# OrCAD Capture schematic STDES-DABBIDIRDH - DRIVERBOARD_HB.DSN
size D
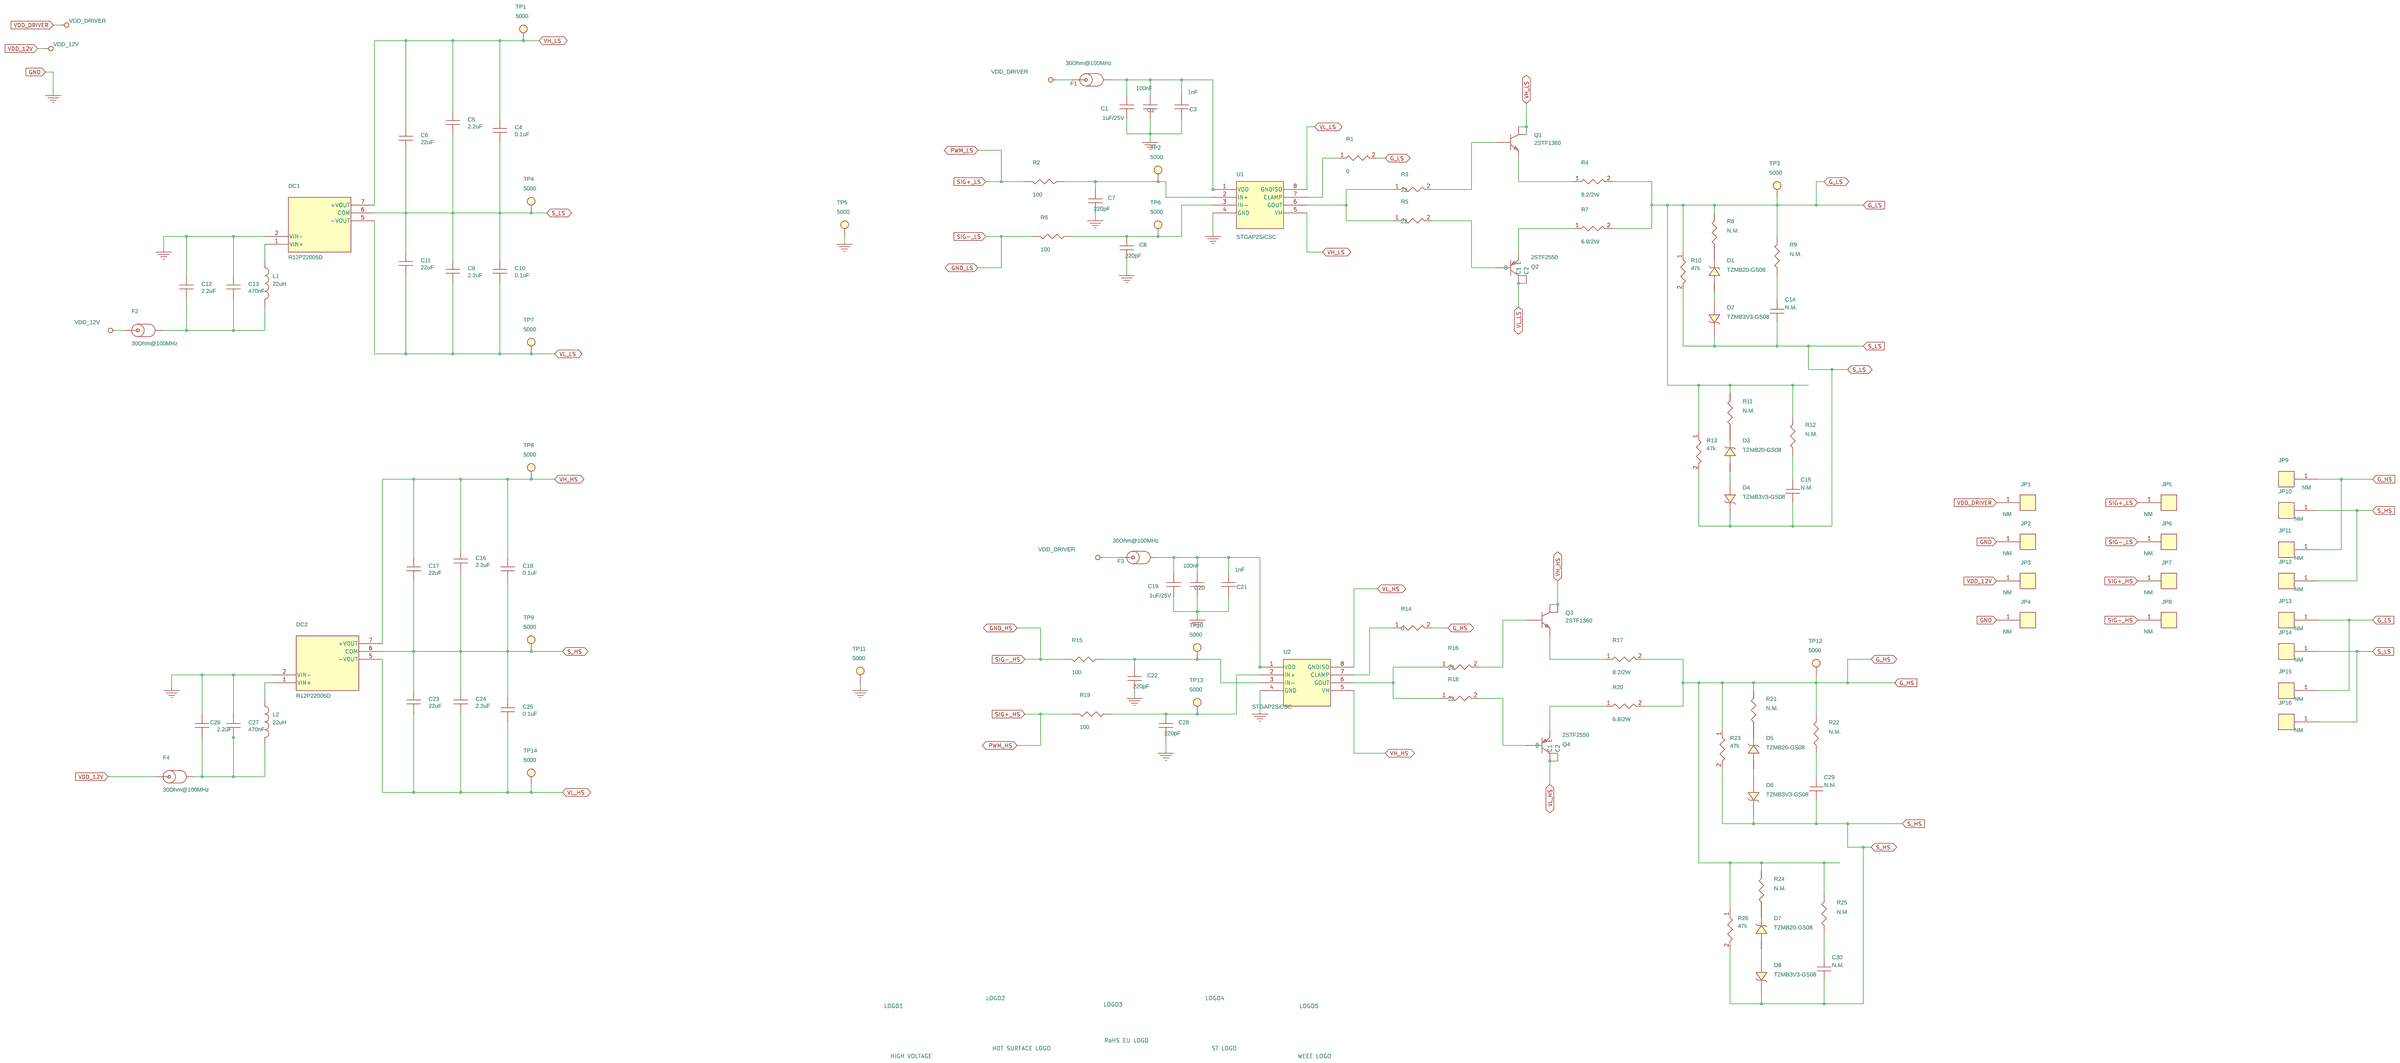
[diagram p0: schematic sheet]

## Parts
C1  1uF/25V  [c_0603]
C2  100nF  [c_0603]
C3  1nF  [C_0603]
C4  0.1uF  [C_0603]
C5  2.2uF  [C_0805]
C6  22uF  [C_1210]
C7  220pF  [c_0603]
C8  220pF  [c_0603]
C9  2.2uF  [C_0805]
C10  0.1uF  [C_0603]
C11  22uF  [C_1210]
C12  2.2uF  [C_0805]
C13  470nF  [C_0805]
C14  N.M.  [C_0603]
C15  N.M.  [C_0603]
C16  2.2uF  [C_0805]
C17  22uF  [C_1210]
C18  0.1uF  [C_0603]
C19  1uF/25V  [c_0603]
C20  100nF  [c_0603]
C21  1nF  [C_0603]
C22  220pF  [c_0603]
C23  22uF  [C_1210]
C24  2.2uF  [C_0805]
C25  0.1uF  [C_0603]
C26  2.2uF  [C_0805]
C27  470nF  [C_0805]
C28  220pF  [c_0603]
C29  N.M.  [C_0603]
C30  N.M.  [C_0603]
D1  TZMB20-GS08  [DIODE_DO-213AC_SOD-80]
D2  TZMB3V3-GS08  [DIODE_DO-213AC_SOD-80]
D3  TZMB20-GS08  [DIODE_DO-213AC_SOD-80]
D4  TZMB3V3-GS08  [DIODE_DO-213AC_SOD-80]
D5  TZMB20-GS08  [DIODE_DO-213AC_SOD-80]
D6  TZMB3V3-GS08  [DIODE_DO-213AC_SOD-80]
D7  TZMB20-GS08  [DIODE_DO-213AC_SOD-80]
D8  TZMB3V3-GS08  [DIODE_DO-213AC_SOD-80]
DC1  R12P22005D  [DCDC_Recom_RxxP2]
DC2  R12P22005D  [DCDC_Recom_RxxP2]
F1  30Ohm@100MHz  [L_0805]
F2  30Ohm@100MHz  [L_0805]
F3  30Ohm@100MHz  [L_0805]
F4  30Ohm@100MHz  [L_0805]
JP1  NM  [3560-1-00-15-00-00-03-0]
JP2  NM  [3560-1-00-15-00-00-03-0]
JP3  NM  [3560-1-00-15-00-00-03-0]
JP4  NM  [3560-1-00-15-00-00-03-0]
JP5  NM  [3560-1-00-15-00-00-03-0]
JP6  NM  [3560-1-00-15-00-00-03-0]
JP7  NM  [3560-1-00-15-00-00-03-0]
JP8  NM  [3560-1-00-15-00-00-03-0]
JP9  NM  [3560-1-00-15-00-00-03-0]
JP10  NM  [3560-1-00-15-00-00-03-0]
JP11  NM  [3560-1-00-15-00-00-03-0]
JP12  NM  [3560-1-00-15-00-00-03-0]
JP13  NM  [3560-1-00-15-00-00-03-0]
JP14  NM  [3560-1-00-15-00-00-03-0]
JP15  NM  [3560-1-00-15-00-00-03-0]
JP16  NM  [3560-1-00-15-00-00-03-0]
L1  22uH  [L_0805]
L2  22uH  [L_0805]
LOGO1  HIGH VOLTAGE  [High-Voltage-Logo10mm]
LOGO2  HOT SURFACE LOGO  [Hot-Surface-Logo8mm]
LOGO3  RoHS EU LOGO  [rohs-eu-logo13mm]
LOGO4  ST LOGO  [STLogo12mm]
LOGO5  WEEE LOGO  [weee12mm]
Q1  2STF1360  [sot89-4p142_409x160l104x50n]
Q2  2STF2550  [sot89-4p142_409x160l104x50n]
Q3  2STF1360  [sot89-4p142_409x160l104x50n]
Q4  2STF2550  [sot89-4p142_409x160l104x50n]
R1  0  [r_1210]
R2  100  [r_0603]
R3  22  [r_1210]
R4  8.2/2W  [r_2512]
R5  22  [r_1210]
R6  100  [r_0603]
R7  6.8/2W  [r_2512]
R8  N.M.  [r_0603]
R9  N.M.  [r_0603]
R10  47k  [r_0603]
R11  N.M.  [r_0603]
R12  N.M.  [r_0603]
R13  47k  [r_0603]
R14  0  [r_1210]
R15  100  [r_0603]
R16  22  [r_1210]
R17  8.2/2W  [r_2512]
R18  22  [r_1210]
R19  100  [r_0603]
R20  6.8/2W  [r_2512]
R21  N.M.  [r_0603]
R22  N.M.  [r_0603]
R23  47k  [r_0603]
R24  N.M.  [r_0603]
R25  N.M.  [r_0603]
R26  47k  [r_0603]
TP1  5000  [testpointd100red]
TP2  5000  [testpointd100red]
TP3  5000  [testpointd100red]
TP4  5000  [testpointd100red]
TP5  5000  [testpointd100red]
TP6  5000  [testpointd100red]
TP7  5000  [testpointd100red]
TP8  5000  [testpointd100red]
TP9  5000  [testpointd100red]
TP10  5000  [testpointd100red]
TP11  5000  [testpointd100red]
TP12  5000  [testpointd100red]
TP13  5000  [testpointd100red]
TP14  5000  [testpointd100red]
U1  STGAP2SiCSC  [soic8p127_584x1031x264l76x40n]
U2  STGAP2SiCSC  [soic8p127_584x1031x264l76x40n]

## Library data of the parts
C1 C19 = CAP_NP: CAPACITOR CERAMIC SMD 0603 (MLCC) GRM 1µF, ±10%, 25V cc, SMD; Any Equivalent?: YES; Distributor code: ANY; Manufacturer: Wurth Electronics Inc.; Manufacturer PN: 885012206076; Manufacturer code: ANY; Package: 0603; Package Size: 0603 (1608 Metric); Rated Voltage: 25V; Tecnology: X7R Ceramic Capacitor; Type Component: CAPACITOR; Voltage/Current: 25V; tolerance: 10%
C2 C20 = CAP_NP: CAPACITOR CERAMIC SMD 0603 (MLCC) GRM 100nF, ±10%, 25V cc, SMD; Any Equivalent?: YES; Distributor code: ANY; Manufacturer: Wurth Electronics Inc.; Manufacturer PN: 885012206071; Manufacturer code: ANY; Package: 0603; Package Size: 0603 (1608 Metric); Rated Voltage: 25V; Tecnology: X7R Ceramic Capacitor; Type Component: CAPACITOR; Voltage/Current: 25V; tolerance: 10%
C3 C21 = CAP: CAPACITOR CERAMIC SMD 0603 (MLCC) C 1nF, ±10%, 25V cc, SMD; Any Equivalent?: YES; CLASS: DISCRETE; Dielectric Type: Capacitors; Distributor code: 147-342; Manufacturer: Wurth Electronics Inc.; Manufacturer PN: 885012006044; PART_NUMBER: CAP-00000070; Package Size: 0603 (1608 Metric); Rated Voltage: 25V; Temperature Coefficient: X7R; Tolerance: 10%
C4 C10 C18 C25 = CAP: CAP CER 0.1UF 50V X7R 0603; Any Equivalent?: YES; CLASS: DISCRETE; Dielectric Type: Capacitors; Manufacturer: Wurth Electronics Inc.; Manufacturer PN: 885012206095; PART_NUMBER: TMP-329; Package Size: 0603 (1608 Metric); Rated Voltage: 50V; Temperature Coefficient: X7R; Tolerance: 5%
C5 C9 C12 C16 C24 C26 = CAP: CAP CER 2.2UF 50V X7R 0805; Any Equivalent?: YES; CLASS: DISCRETE; Dielectric Type: Capacitors; Manufacturer: Wurth Electronics Inc.; Manufacturer PN: 885012207079; PART_NUMBER: CAP-00000034; Package Size: 0805 (2012 Metric); Rated Voltage: 25V; Temperature Coefficient: X7R; Tolerance: 10%
C6 C11 C17 C23 = CAP: CAP CER 22UF 25V X5R 1210; Any Equivalent?: YES; CLASS: DISCRETE; Manufacturer: Würth Elektronik; Manufacturer PN: 885012109014; PART_NUMBER: CAP-00000421; Package Size: 1210 (3225 Metric); Rated Voltage: 25V; Temperature Coefficient: X5R; Tolerance: 20%
C7 C8 C22 C28 = CAP_NP: CAPACITOR CERAMIC SMD 0603 (MLCC) C 220pF, ±5%, 1kV cc, SMD; Any Equivalent?: YES; Distributor code: ANY; Manufacturer: Wurth Electronics Inc.; Manufacturer PN: 885012006059; Manufacturer code: ANY; Package: 0603; Package Size: 0603 (1608 Metric); Rated Voltage: 50V; Tecnology: X7R Ceramic Capacitor; Type Component: CAPACITOR; Voltage/Current: 50V; tolerance: 5%
C13 C27 = CAP: CAPACITOR CERAMIC SMD 0805; ALT_SYMBOLS: C_0805_hd; Any Equivalent?: YES; CLASS: DISCRETE; Dielectric Type: Capacitors; Manufacturer: Wurth Electronics Inc.; Manufacturer PN: 885012207102; PART_NUMBER: CAP-00000192; Package Size: 0805 (2012 Metric); Rated Voltage: 50V; Tolerance: 10%
C14 C15 C29 C30 = CAP_NP: Any Equivalent?: YES; Manufacturer: ANY; Manufacturer code: ANY; Package: 0603; Tecnology: X7R Ceramic Capacitor
D1 D3 D5 D7 = DIODE_ZENER: DIODE ZENER 20V 500MW SOD80; Any Equivalent?: YES; CLASS: DISCRETE; Manufacturer: Vishay Semiconductor Diodes Division; PART_NUMBER: TMP-670; Package Size: DO-213AC, MINI-MELF, SOD-80
D2 D4 D6 D8 = DIODE_ZENER: DIODE ZENER 3.3V 500MW SOD80; Any Equivalent?: YES; CLASS: DISCRETE; Manufacturer: Vishay Semiconductor Diodes Division; PART_NUMBER: TMP-671; Package Size: DO-213AC, MINI-MELF, SOD-80
DC1 DC2 = DCDC_Recom_RxxP2: CONV DC/DC 2W 12VIN +20/-5VOUT T; Any Equivalent?: NO; CLASS: IC; Manufacturer: RECOM; PART_NUMBER: TMP-672; Package Size: 0.77" L x 0.39" W x 0.49" H (19.5mm x 9.8mm x 12.5mm)
F1-F4 = IND_FB: FERRITE BEAD 30 OHM 0805 1LN; Any Equivalent?: YES; CLASS: DISCRETE; Distributor code: 740-9066; Manufacturer: Wurth Electronics Inc.; Manufacturer PN: 742792030; NOTE: sostituito con resistenza SMD 0 ohm; PART_NUMBER: TMP-661; Package Size: 0805 (2012 Metric)
JP1-JP16 = 3560-1-00-15-00-00-03-0: IC & Component Sockets .060" Dia St Pins; Any Equivalent?: NO; Manufacturer: Mill-Max
L1 L2 = IND: FIXED IND 22UH 130MA 3.7 OHM SMD; Any Equivalent?: NO; CLASS: DISCRETE; Manufacturer: Taiyo Yuden; Manufacturer PN: LBC2012T220M; PART_NUMBER: IND-00000051; Package Size: 0805 (2012 Metric); Tolerance: 20%
LOGO1 = HIGH_VOLTAGE: HIGH VOLTAGE LOGO - SILKSCREEN; ALT_SYMBOLS: high-voltage-logo7mm,HIGH-VOLTAGE-LOGO6MM,high-voltage-logo5mm,High-Voltage-Text-Logo; Any Equivalent?: NO; CLASS: Mechanical; PART_NUMBER: MIS-00000028
LOGO2 = LOGO_HOT_SURFACE: HOT SURFACE LOGO - SILKSCREEN; ALT_SYMBOLS: Hot-Surface-Logo10mm,Hot-Surface-Logo12mm; Any Equivalent?: NO; CLASS: Mechanical; PART_NUMBER: MIS-00000011
LOGO3 = RoHS_EU: RoHS EU - SILKSCREEN; ALT_SYMBOLS: rohs-eu-logo9mm,RoHS-Eu-Logo7mm,RoHS-Eu-Logo5mm; Any Equivalent?: NOT; CLASS: Mechanical; PART_NUMBER: MIS-00000007
LOGO4 = LOGO_ST: ST LOGO - SILKSCREEN; ALT_SYMBOLS: stlogo11mm,STLogo10mm,STLogo9mm,STLogo8mm,STLogo7mm,STLogo6mm,STLogo5mm,stlogo4mm; CLASS: Mechanical; PART_NUMBER: MECH-00000001
LOGO5 = WEEE: WEEE LOGO - SILKSCREEN; ALT_SYMBOLS: weee10mm,weee8mm,weee7mm; CLASS: Mechanical; PART_NUMBER: LOGO-00000001
Q1 Q3 = BJT_NPN_BCEC_4P: TRANS NPN 60V 3A SOT-89; Any Equivalent?: NO; CLASS: DISCRETE; Manufacturer: STMicroelectronics; PART_NUMBER: TMP-669; Package Size: TO-243AA; Polarity: NPN
Q2 Q4 = BJT_PNP_BCEC_4P: TRANS PNP 50V 5A SOT 89; Any Equivalent?: NO; CLASS: DISCRETE; Manufacturer: STMicroelectronics; PART_NUMBER: TMP-695; Package Size: TO-243AA; Polarity: PNP
R1 R3 R5 R14 R16 R18 = RES: CHIP RESISTOR SMD; Any Equivalent?: YES; PART_NUMBER: Gen_R-000006; Package Size: 1210 (3225 Metric)
R2 R6 R15 R19 = R: Resistore SMD Bourns 100O ±1%, 0,1W, 0603, serie CR0603; Any Equivalent?: YES; Distributor code: ANY; Manufacturer: ANY; Manufacturer PN: ANY; Manufacturer code: ANY; Package: 0603; Tecnology: Metal film resistor; Type Component: RESISTOR; Voltage/Current: 50V; Watt: 1/10; tolerance: 1%
R4 R7 R17 R20 = RES: CHIP RESISTOR SMD; Any Equivalent?: YES; PART_NUMBER: Gen_R-000008; Package Size: 2512 (6332 metric)
R8 R9 R11 R12 R21 R22 R24 R25 = R: Any Equivalent?: YES; Package: 0603; Tecnology: Metal film resistor; Type Component: RESISTOR
R10 R13 R23 R26 = RES: CHIP RESISTOR SMD 1% 1/10W 0603; ALT_SYMBOLS: r_0603_hd; Any Equivalent?: YES; PART_NUMBER: Gen_R-000003; Package Size: 0603 (1608 Metric); Rated Power: 0.1W, 1/10W; Tolerance: 1%
TP1-TP14 = TESTPOINT: TEST POINT PC MINI .040"D RED; Any Equivalent?: YES; CLASS: IO; Manufacturer: ANY; Manufacturer PN: ANY; PART_NUMBER: CON-00000188; Package Size: 0.100" Dia x 0.180" L (2.54mm x 4.57mm)
U1 U2 = STGAP2SiCSC: Galvanically isolated 4 A single gate driver for SiC MOSFETs; Any Equivalent?: NO; CLASS: IC; Manufacturer: STMicroelectronics; PART_NUMBER: IC-00000131; STEP_MODEL: SOIC8P127_584X1031X264L76X40

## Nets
GND: C1.2 C2.2 C3.2 C7.2 C8.2 C12.1 C13.1 C19.2 C20.2 C21.2 C22.2 C26.1 C27.1 C28.2 DC1.2(VIN-) DC2.2(VIN-) JP2.1 JP4.1 TP5.1 TP11.1 U1.4(GND) U2.4(GND)
GND_HS: JP8.1 R15.2
GND_LS: JP6.1 R6.2
VDD_12V: F2.1 F4.1 JP3.1
VDD_DRIVER: F1.1 F3.1 JP1.1
G_HS: JP9.1 JP11.1 R14.2 R17.2 R20.2 R21.2 R22.2 R23.1 R24.2 R25.2 R26.1 TP12.1
G_LS: JP13.1 JP15.1 R1.2 R4.2 R7.2 R8.2 R9.2 R10.1 R11.2 R12.2 R13.1 TP3.1
PWM_HS: JP7.1 R19.2
PWM_LS: JP5.1 R2.2
S_HS: C16.2 C17.2 C18.2 C23.1 C24.1 C25.1 C29.1 C30.1 D6.C D8.C DC2.6(COM) JP10.1 JP12.1 R23.2 R26.2 TP9.1
S_LS: C4.2 C5.2 C6.2 C9.1 C10.1 C11.1 C14.1 C15.1 D2.C D4.C DC1.6(COM) JP14.1 JP16.1 R10.2 R13.2 TP4.1
VH_HS: C16.1 C17.1 C18.1 DC2.7(+VOUT) Q3.2(C1) Q3.4(C) TP8.1 U2.5(VH)
VH_LS: C4.1 C5.1 C6.1 DC1.7(+VOUT) Q1.2(C1) Q1.4(C) TP1.1 U1.5(VH)
VL_HS: C23.2 C24.2 C25.2 DC2.5(-VOUT) Q4.2(C1) Q4.4(C2) TP14.1 U2.8(GNDISO)
VL_LS: C9.2 C10.2 C11.2 DC1.5(-VOUT) Q2.2(C1) Q2.4(C2) TP7.1 U1.8(GNDISO)
N16765017: C1.1 C2.1 C3.1 F1.2 U1.1(VDD)
N16765409: R1.1 U1.7(CLAMP)
N16765429: C7.1 R2.1 TP2.1 U1.2(IN+)
N16765547: R3.1 R5.1 U1.6(GOUT)
N16765661: C8.1 R6.1 TP6.1 U1.3(IN-)
N16765953: DC1.1(VIN+) L1.1
N16766145: C14.2 R9.1
N16766205: D1.A D2.A
N16766213: C12.2 C13.2 F2.2 L1.2
N16766605: C19.1 C20.1 C21.1 F3.2 U2.1(VDD)
N16766995: R14.1 U2.7(CLAMP)
N16767019: C22.1 R15.1 TP10.1 U2.3(IN-)
N16767137: R16.1 R18.1 U2.6(GOUT)
N16767145: Q3.1(B) R16.2
N16767193: C28.1 R19.1 TP13.1 U2.2(IN+)
N16767217: DC2.1(VIN+) L2.1
N16767383: Q4.1(B) R18.2
N16767595: C26.2 C27.2 F4.2 L2.2
N16767699: C29.2 R22.1
N16767741: D5.A D6.A
N16812872: Q1.1(B) R3.2
N16812876: Q1.3(E) R4.1
N16812900: Q2.1(B) R5.2
N16812914: Q2.3(E) R7.1
N16814114: Q3.3(E) R17.1
N16814152: Q4.3(E) R20.1
N16822999: C30.2 R25.1
N16823003: D7.A D8.A
N16823292: C15.2 R12.1
N16823296: D3.A D4.A
N16838108: D3.C R11.1
N16838113: D1.C R8.1
N16838114: D7.C R24.1
N16838116: D5.C R21.1
